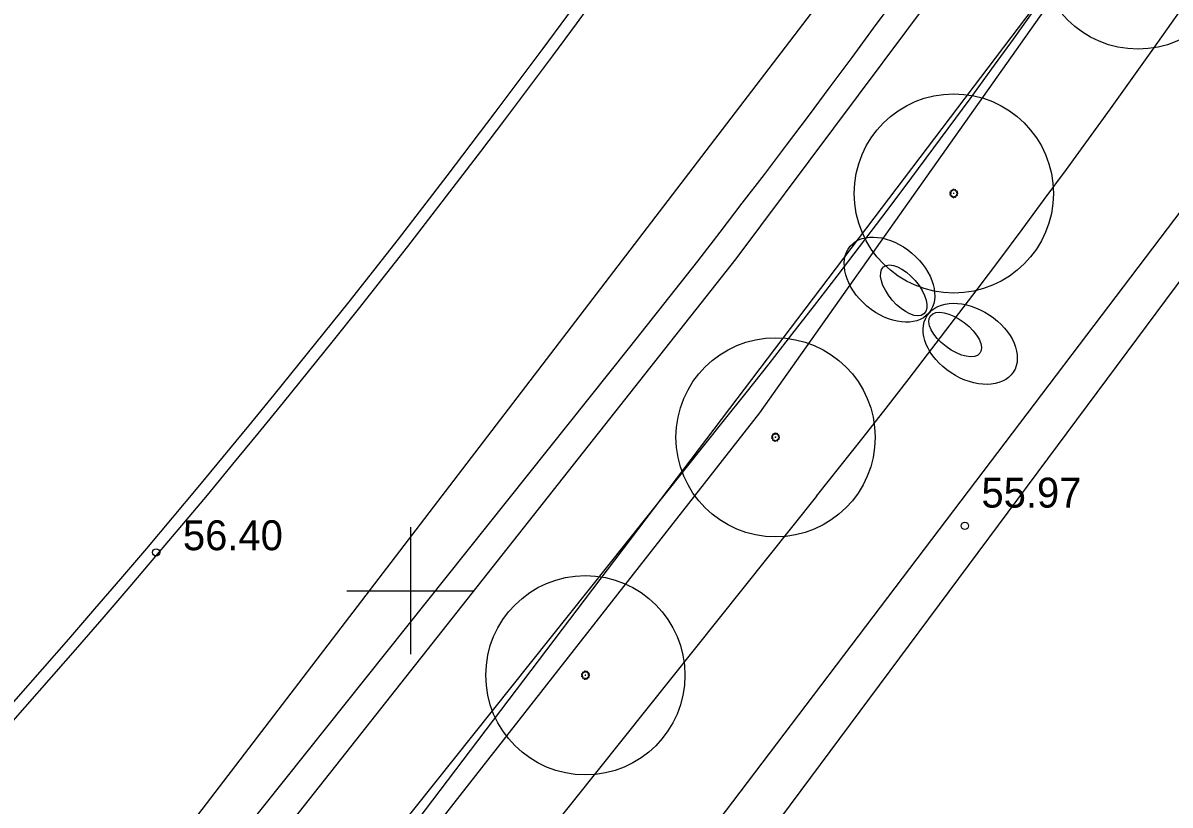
# Model space of a CAD drawing. Extents: x 9156 to 9809, y 2728 to 4000.
# Drawn here: x 9440.27 to 9469.07, y 3544.62 to 3564.25 of the extents above; entities that cross this region are included whole.
import ezdxf

# ---------------------------------------------------------------- set-up
doc = ezdxf.new("R2010")
doc.units = 0
for name, color, linetype in [('Level 11', 7, 'Continuous'), ('Level 12', 7, 'Continuous'), ('Level 14', 7, 'Continuous'), ('Level 15', 7, 'Continuous'), ('Level 16', 7, 'Continuous'), ('Level 17', 7, 'Continuous'), ('Level 18', 7, 'Continuous'), ('Level 54', 7, 'Continuous'), ('Level 56', 7, 'Continuous'), ('Level 58', 7, 'Continuous'), ('Level 6', 7, 'Continuous'), ('Level 7', 7, 'Continuous'), ('Level 8', 7, 'Continuous'), ('Level 9', 7, 'Continuous')]:
    doc.layers.add(name, color=color, linetype=linetype)

# ---------------------------------------------------------------- blocks, each defined once
blk = doc.blocks.new('KKOL')
at = {"layer": 'Level 58'}
for p, q in [((0, 1.59349), (0, -1.5935)), ((-1.5935, 0), (1.59349, 0))]:
    blk.add_line(p, q, dxfattribs=at)

msp = doc.modelspace()

# ---------------------------------------------------------------- linework, layer by layer
at = {"layer": 'Level 11'}
msp.add_arc((9257.773, 3708.522), 243.4, 317.80433, 332.882, dxfattribs=at)
msp.add_arc((9257.773, 3708.522), 243.4, 317.80433, 332.882, dxfattribs=at)
at = {"layer": 'Level 12'}
msp.add_line((9472.329, 3573.455), (9435.481, 3524.854), dxfattribs=at)
at = {"layer": 'Level 14'}
msp.add_line((9427.489, 3501.526), (9484.383, 3578.032), dxfattribs=at)
at = {"layer": 'Level 15'}
for p, q in [((9458.77, 3554.464), (9476.288, 3579.24)), ((9435.211, 3524.4), (9458.77, 3554.464))]:
    msp.add_line(p, q, dxfattribs=at)
at = {"layer": 'Level 16'}
msp.add_line((9432.07, 3510.41), (9469.372, 3559.57), dxfattribs=at)
at = {"layer": 'Level 17'}
for p, q in [((9458.182, 3558.332), (9467.092, 3570.267)), ((9427.374, 3519.354), (9458.182, 3558.332)), ((9428.56, 3522.344), (9455.51, 3556.115)), ((9432.973, 3523.064), (9457.855, 3554.244))]:
    msp.add_line(p, q, dxfattribs=at)
for radius in [243.4, 246.4]:
    msp.add_arc((9265.261, 3707.934), radius, 321.41014, 335.20045, dxfattribs=at)
at = {"layer": 'Level 18'}
msp.add_line((9441.751, 3529.254), (9460.2, 3552.373), dxfattribs=at)
msp.add_arc((9265.261, 3707.934), 249.4, 321.41014, 335.20045, dxfattribs=at)
at = {"layer": 'Level 54'}
for p, q in [((9450, 3551.25), (9450, 3548.75)), ((9448.75, 3550), (9451.25, 3550))]:
    msp.add_line(p, q, dxfattribs=at)
for centre in [(9463.921, 3551.63), (9443.616, 3550.963)]:
    msp.add_circle(centre, 0.0909, dxfattribs=at)
at = {"layer": 'Level 56'}
for p, q in [((9428.56, 3522.344), (9455.51, 3556.115)), ((9432.973, 3523.064), (9457.855, 3554.244)), ((9441.751, 3529.254), (9460.2, 3552.373))]:
    msp.add_line(p, q, dxfattribs=at)
for radius in [243.4, 246.4, 249.4]:
    msp.add_arc((9265.261, 3707.934), radius, 321.41014, 335.20045, dxfattribs=at)
at = {"layer": 'Level 6'}
msp.add_arc((9257.773, 3708.522), 243.702, 317.80433, 332.882, dxfattribs=at)
at = {"layer": 'Level 7'}
msp.add_line((9428.759, 3523.586), (9464.86, 3570.761), dxfattribs=at)
at = {"layer": 'Level 8'}
for centre, major_axis, ratio in [((9462.028, 3557.807), (0.986, -0.837), 0.674652), ((9462.028, 3557.807), (0.986, -0.837), 0.674652), ((9462.028, 3557.807), (0.986, -0.837), 0.674652), ((9462.028, 3557.807), (0.986, -0.837), 0.674652), ((9462.386, 3557.538), (0.507, -0.589), 0.486914), ((9462.386, 3557.538), (0.507, -0.589), 0.486914), ((9462.386, 3557.538), (0.507, -0.589), 0.486914), ((9462.386, 3557.538), (0.507, -0.589), 0.486914), ((9464.055, 3556.196), (-1.081, 0.71), 0.674652), ((9464.055, 3556.196), (-1.081, 0.71), 0.674652), ((9464.055, 3556.196), (-1.081, 0.71), 0.674652), ((9464.055, 3556.196), (-1.081, 0.71), 0.674652), ((9463.677, 3556.429), (-0.62, 0.47), 0.486914), ((9463.677, 3556.429), (-0.62, 0.47), 0.486914), ((9463.677, 3556.429), (-0.62, 0.47), 0.486914), ((9463.677, 3556.429), (-0.62, 0.47), 0.486914)]:
    msp.add_ellipse(centre, major_axis=major_axis, ratio=ratio, dxfattribs=at)
at = {"layer": 'Level 9'}
for p, q in [((9463.565, 3559.984), (9463.544, 3559.987)), ((9463.544, 3559.958), (9463.565, 3559.962)), ((9463.552, 3560.014), (9463.572, 3560.006)), ((9463.571, 3559.94), (9463.552, 3559.93)), ((9463.584, 3560.024), (9463.567, 3560.038)), ((9463.567, 3559.907), (9463.583, 3559.921)), ((9463.589, 3560.057), (9463.6, 3560.038)), ((9463.601, 3559.906), (9463.589, 3559.888)), ((9463.614, 3559.876), (9463.62, 3559.897)), ((9463.622, 3560.048), (9463.615, 3560.069)), ((9463.654, 3559.971), (9463.633, 3559.971)), ((9463.643, 3559.893), (9463.642, 3559.872)), ((9463.643, 3560.073), (9463.643, 3560.051)), ((9463.643, 3559.961), (9463.643, 3559.982)), ((9463.665, 3560.048), (9463.671, 3560.069)), ((9463.671, 3559.876), (9463.665, 3559.897)), ((9463.685, 3559.906), (9463.697, 3559.887)), ((9463.697, 3560.057), (9463.686, 3560.038)), ((9463.703, 3560.024), (9463.719, 3560.038)), ((9463.72, 3559.907), (9463.704, 3559.922)), ((9463.735, 3560.014), (9463.715, 3560.004)), ((9463.715, 3559.94), (9463.735, 3559.931)), ((9463.721, 3559.983), (9463.743, 3559.987)), ((9463.743, 3559.959), (9463.721, 3559.962)), ((9459.09, 3553.863), (9459.068, 3553.866)), ((9459.068, 3553.837), (9459.09, 3553.841)), ((9459.077, 3553.893), (9459.097, 3553.885)), ((9459.109, 3553.903), (9459.092, 3553.917)), ((9459.113, 3553.936), (9459.125, 3553.917)), ((9459.146, 3553.927), (9459.14, 3553.948)), ((9459.179, 3553.85), (9459.158, 3553.85)), ((9459.168, 3553.952), (9459.168, 3553.93)), ((9459.168, 3553.84), (9459.168, 3553.861)), ((9459.189, 3553.927), (9459.195, 3553.948)), ((9459.222, 3553.936), (9459.211, 3553.917)), ((9459.227, 3553.903), (9459.244, 3553.917)), ((9459.26, 3553.893), (9459.24, 3553.883)), ((9459.246, 3553.862), (9459.267, 3553.866)), ((9459.268, 3553.838), (9459.246, 3553.841)), ((9459.096, 3553.819), (9459.077, 3553.809)), ((9459.092, 3553.786), (9459.108, 3553.8)), ((9459.126, 3553.785), (9459.113, 3553.767)), ((9459.139, 3553.755), (9459.145, 3553.776)), ((9459.168, 3553.773), (9459.167, 3553.751)), ((9459.196, 3553.755), (9459.19, 3553.776)), ((9459.21, 3553.785), (9459.222, 3553.767)), ((9459.245, 3553.786), (9459.228, 3553.801)), ((9459.24, 3553.819), (9459.26, 3553.811)), ((9454.316, 3547.891), (9454.295, 3547.894)), ((9454.295, 3547.866), (9454.316, 3547.869)), ((9454.303, 3547.922), (9454.323, 3547.914)), ((9454.323, 3547.847), (9454.303, 3547.837)), ((9454.335, 3547.932), (9454.318, 3547.946)), ((9454.318, 3547.814), (9454.334, 3547.829)), ((9454.34, 3547.964), (9454.351, 3547.946)), ((9454.352, 3547.813), (9454.34, 3547.795)), ((9454.365, 3547.783), (9454.371, 3547.804)), ((9454.373, 3547.956), (9454.366, 3547.976)), ((9454.405, 3547.879), (9454.384, 3547.879)), ((9454.394, 3547.98), (9454.394, 3547.959)), ((9454.394, 3547.868), (9454.394, 3547.889)), ((9454.394, 3547.801), (9454.394, 3547.779)), ((9454.416, 3547.956), (9454.422, 3547.977)), ((9454.422, 3547.783), (9454.417, 3547.804)), ((9454.436, 3547.813), (9454.449, 3547.795)), ((9454.448, 3547.965), (9454.438, 3547.946)), ((9454.454, 3547.932), (9454.47, 3547.946)), ((9454.471, 3547.815), (9454.455, 3547.829)), ((9454.486, 3547.922), (9454.466, 3547.912)), ((9454.466, 3547.848), (9454.486, 3547.839)), ((9454.472, 3547.891), (9454.494, 3547.895)), ((9454.494, 3547.866), (9454.473, 3547.87))]:
    msp.add_line(p, q, dxfattribs=at)
for centre in [(9468.268, 3566.092), (9463.643, 3559.971), (9459.168, 3553.85), (9454.394, 3547.879)]:
    msp.add_circle(centre, 2.5, dxfattribs=at)
for centre, radius, start, end in [((9463.643, 3559.972), 0.101, 155.3123, 171.7042), ((9463.643, 3559.972), 0.101, 187.9671, 204.8625), ((9463.643, 3559.972), 0.0788, 171.5431, 187.6203), ((9463.643, 3559.972), 0.101, 122.8434, 139.0222), ((9463.643, 3559.972), 0.101, 220.7122, 237.1166), ((9463.643, 3559.972), 0.0788, 204.4529, 220.4774), ((9463.643, 3559.972), 0.0788, 138.6432, 154.5795), ((9463.643, 3559.972), 0.0788, 105.9559, 123.0564), ((9463.643, 3559.972), 0.0788, 237.451, 253.0843), ((9463.643, 3559.972), 0.101, 90.0356, 106.342), ((9463.643, 3559.972), 0.0788, 74.31, 90.043), ((9463.643, 3559.972), 0.0788, 269.9461, 286.3473), ((9463.643, 3559.972), 0.101, 57.6108, 74.1981), ((9463.643, 3559.972), 0.101, 285.972, 302.5562), ((9463.643, 3559.972), 0.0788, 302.254, 320.086), ((9463.643, 3559.972), 0.0788, 41.2062, 56.7795), ((9463.643, 3559.972), 0.0788, 8.0619, 24.0332), ((9463.643, 3559.972), 0.0788, 336.0557, 352.7558), ((9463.643, 3559.972), 0.101, 24.5394, 40.9852), ((9463.643, 3559.972), 0.101, 319.7777, 336.0738), ((9463.643, 3559.972), 0.101, 352.27, 8.583), ((9463.643, 3559.972), 0.101, 253.2952, 269.5718), ((9459.168, 3553.851), 0.101, 155.3123, 171.7042), ((9459.168, 3553.851), 0.101, 187.9671, 204.8625), ((9459.168, 3553.851), 0.0788, 171.5431, 187.6203), ((9459.168, 3553.851), 0.101, 122.8434, 139.0222), ((9459.168, 3553.851), 0.0788, 138.6432, 154.5795), ((9459.168, 3553.851), 0.0788, 105.9559, 123.0564), ((9459.168, 3553.851), 0.101, 90.0356, 106.342), ((9459.168, 3553.851), 0.0788, 74.31, 90.043), ((9459.168, 3553.851), 0.101, 57.6108, 74.1981), ((9459.168, 3553.851), 0.0788, 41.2062, 56.7795), ((9459.168, 3553.851), 0.0788, 8.0619, 24.0332), ((9459.168, 3553.851), 0.0788, 336.0557, 352.7558), ((9459.168, 3553.851), 0.101, 24.5394, 40.9852), ((9459.168, 3553.851), 0.101, 352.27, 8.583), ((9459.168, 3553.851), 0.101, 220.7122, 237.1166), ((9459.168, 3553.851), 0.0788, 204.4529, 220.4774), ((9459.168, 3553.851), 0.0788, 237.451, 253.0843), ((9459.168, 3553.851), 0.101, 253.2952, 269.5718), ((9459.168, 3553.851), 0.0788, 269.9461, 286.3473), ((9459.168, 3553.851), 0.101, 285.972, 302.5562), ((9459.168, 3553.851), 0.0788, 302.254, 320.086), ((9459.168, 3553.851), 0.101, 319.7777, 336.0738), ((9454.394, 3547.88), 0.101, 155.3123, 171.7042), ((9454.394, 3547.88), 0.101, 187.9671, 204.8625), ((9454.394, 3547.88), 0.0788, 171.5431, 187.6203), ((9454.394, 3547.88), 0.101, 122.8434, 139.0222), ((9454.394, 3547.88), 0.101, 220.7122, 237.1166), ((9454.394, 3547.88), 0.0788, 138.6432, 154.5795), ((9454.394, 3547.88), 0.0788, 204.4529, 220.4774), ((9454.394, 3547.88), 0.0788, 105.9559, 123.0564), ((9454.394, 3547.88), 0.0788, 237.451, 253.0843), ((9454.394, 3547.88), 0.101, 253.2952, 269.5718), ((9454.394, 3547.88), 0.101, 90.0356, 106.342), ((9454.394, 3547.88), 0.0788, 74.31, 90.043), ((9454.394, 3547.88), 0.0788, 269.9461, 286.3473), ((9454.394, 3547.88), 0.101, 57.6108, 74.1981), ((9454.394, 3547.88), 0.101, 285.972, 302.5562), ((9454.394, 3547.88), 0.0788, 302.254, 320.086), ((9454.394, 3547.88), 0.0788, 41.2062, 56.7795), ((9454.394, 3547.88), 0.0788, 8.0619, 24.0332), ((9454.394, 3547.88), 0.0788, 336.0557, 352.7558), ((9454.394, 3547.88), 0.101, 24.5394, 40.9852), ((9454.394, 3547.88), 0.101, 319.7777, 336.0738), ((9454.394, 3547.88), 0.101, 352.27, 8.583)]:
    msp.add_arc(centre, radius, start, end, dxfattribs=at)

# ---------------------------------------------------------------- block references
at = {"layer": 'Level 54'}
msp.add_blockref('KKOL', (9450, 3550), dxfattribs=at)

# ---------------------------------------------------------------- texts
for s, p in [('55.97', (9464.337, 3552.087)), ('56.40', (9444.289, 3551.017))]:
    msp.add_text(s, height=0.75, dxfattribs=at).set_placement(p)

doc.saveas('drawing.dxf')
